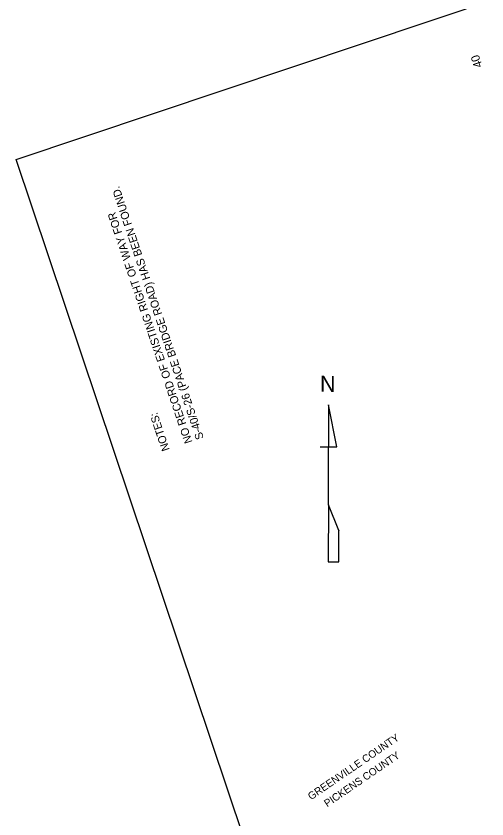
# Model space of a CAD drawing. Extents: x 1528853 to 1624411, y 1119753 to 1162242.
# Drawn here: x 1528853 to 1529294, y 1160305 to 1161058 of the extents above; entities that cross this region are included whole.
import ezdxf

# ---------------------------------------------------------------- set-up
doc = ezdxf.new("R2010")
doc.units = 0
for name, color, linetype in [('RD_EX_DV_TX_Gov', 7, 'Continuous'), ('RD_HC_Data', 7, 'Continuous'), ('RD_HC_TX_Sta50', 7, 'Continuous'), ('RD_SHT_ShtClip', 7, 'Continuous'), ('RD_SHT_TX', 7, 'Continuous')]:
    doc.layers.add(name, color=color, linetype=linetype)

msp = doc.modelspace()

# ---------------------------------------------------------------- linework, layer by layer
at = {"layer": 'RD_SHT_ShtClip'}
for p, q in [((1528852.95, 1160923.06), (1529895.79, 1161273.06)), ((1529473.4, 1159074.4), (1528852.95, 1160923.06))]:
    msp.add_line(p, q, dxfattribs=at)
at = {"layer": 'RD_SHT_TX'}
for p, q in [((1529145.65, 1160693.26), (1529145.56, 1160654.06)), ((1529153.4, 1160654.04), (1529145.65, 1160693.26)), ((1529145.65, 1160693.26), (1529145.65, 1160693.26)), ((1529153.4, 1160654.04), (1529153.4, 1160654.5)), ((1529137.72, 1160654.08), (1529145.56, 1160654.06)), ((1529145.42, 1160599.66), (1529145.56, 1160654.06)), ((1529145.56, 1160654.06), (1529153.4, 1160654.04)), ((1529145.42, 1160599.66), (1529145.29, 1160546.25)), ((1529155.17, 1160575.63), (1529145.42, 1160599.66)), ((1529155.09, 1160546.23), (1529155.17, 1160575.9)), ((1529155.17, 1160575.9), (1529155.17, 1160575.63)), ((1529145.29, 1160546.25), (1529155.09, 1160546.23))]:
    msp.add_line(p, q, dxfattribs=at)

# ---------------------------------------------------------------- texts
at = {"layer": 'RD_EX_DV_TX_Gov'}
for s, p in [('GREENVILLE COUNTY', (1529129.16, 1160322.77)), ('PICKENS COUNTY', (1529144.29, 1160316.16))]:
    msp.add_text(s, height=7, rotation=34.37436, dxfattribs=at).set_placement(p)
at = {"layer": 'RD_HC_Data'}
for s, p in [('S-40/S-26 (PACE BRIDGE ROAD) HAS BEEN FOUND.', (1529028.87, 1160662.12)), ('NO RECORD OF EXISTING RIGHT OF WAY FOR', (1529018.2, 1160658.54)), ('NOTES:', (1528996.87, 1160651.37))]:
    msp.add_text(s, height=7.5, rotation=108.56801, dxfattribs=at).set_placement(p)
at = {"layer": 'RD_HC_TX_Sta50'}
msp.add_text('40', height=8, rotation=108.56801, dxfattribs=at).set_placement((1529289.8, 1161010.62))
at = {"layer": 'RD_SHT_TX'}
msp.add_text('N', height=15, rotation=359.86146, dxfattribs=at).set_placement((1529137.53, 1160705.49))

doc.saveas('drawing.dxf')
